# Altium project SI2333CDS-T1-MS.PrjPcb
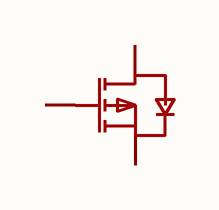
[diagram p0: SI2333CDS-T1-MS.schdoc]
1 sheet, 1 parts. Net scope: global (net labels, ports and power ports of the same name join across sheets).

## Sheet SI2333CDS-T1-MS.schdoc
size 127 x 101 mm

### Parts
Q?  si2333cds-t1-ms  [SOT-23-3_L3.0-W1.6-P1.90-LS2.8-BR]  (value not drawn)

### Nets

Not connected (* = marked no-connect by the designer): Q? 1(G) 2(S) 3(D)

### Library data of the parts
Q? = si2333cds-t1-ms: 数量:1个P沟道;漏源电压(Vdss):18V;连续漏极电流(Id):7A;导通电阻(RDS(on)):22mΩ@4.5V;耗散功率(Pd):1W;阈值电压(Vgs(th)):800mV;; Manufacturer: MSKSEMI(美森科); AddInBom: yes; ModelId: 9c001725612240e7be81cfaae32ec359; ModelTransform: 114.173,116.535,0,0,0,0,0,0,0; Number: 1个P沟道; Drain to Source Voltage: 18V; Current - Continuous Drain(Id): 7A; Pd - Power Dissipation: 1W; Gate Threshold Voltage (Vgs(th)): 800mV; Gate Charge(Qg): 10nC@4.5V; Input Capacitance(Ciss): 1.21nF; Reverse Transfer Capacitance (Crss@Vds): 290pF; Type: P沟道; Output Capacitance(Coss): 310pF; Vgs: ±12V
